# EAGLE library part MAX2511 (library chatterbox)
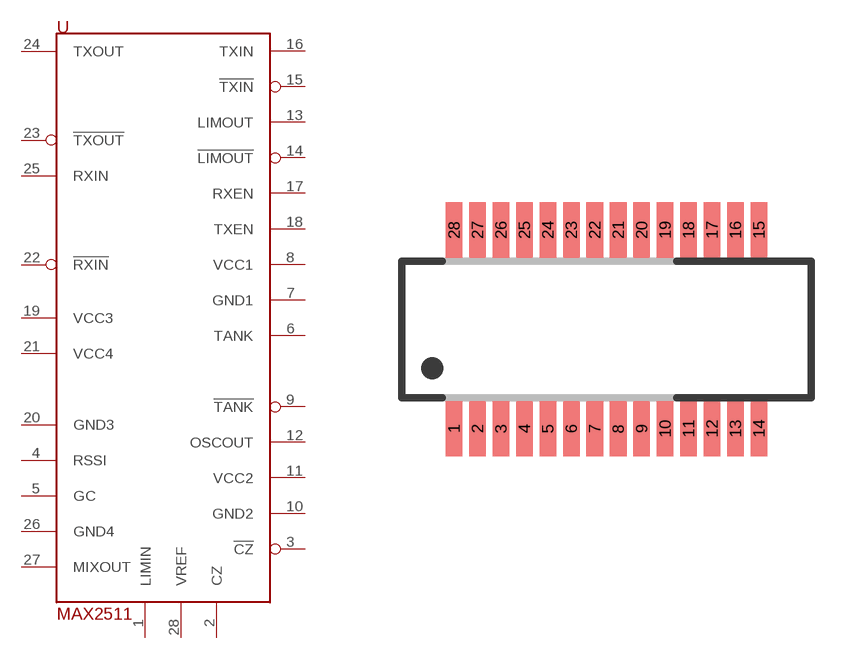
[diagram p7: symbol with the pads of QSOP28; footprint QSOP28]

Designator prefix -

## MAX25110  [QSOP28]
1  LIMIN  pas
2  CZ  pas
3  !CZ  pas
4  RSSI  pas
5  GC  pas
6  TANK  pas
7  GND1  pwr
8  VCC1  pwr
9  !TANK  pas
10  GND2  pwr
11  VCC2  pwr
12  OSCOUT  pas
13  LIMOUT  pas
14  !LIMOUT  pas
15  !TXIN  pas
16  TXIN  pas
17  RXEN  pas
18  TXEN  pas
19  VCC3  pwr
20  GND3  pwr
21  VCC4  pwr
22  !RXIN  pas
23  !TXOUT  pas
24  TXOUT  pas
25  RXIN  pas
26  GND4  pwr
27  MIXOUT  pas
28  VREF  pas

## Footprint QSOP28 (pad centres in mm)
QSOP
smd 0.45 x 1.5: 1 -2.857,-2.69; 2 -2.223,-2.69; 3 -1.587,-2.69; 4 -0.953,-2.69; 5 -0.318,-2.69; 6 0.318,-2.69; 7 0.953,-2.69; 8 1.587,-2.69; 9 2.223,-2.69; 10 2.857,-2.69; 11 3.493,-2.69; 12 4.128,-2.69; 13 4.763,-2.69; 14 5.397,-2.69; 15 5.397,2.69; 16 4.763,2.69; 17 4.128,2.69; 18 3.493,2.69; 19 2.857,2.69; 20 2.223,2.69; 21 1.587,2.69; 22 0.953,2.69; 23 0.318,2.69; 24 -0.318,2.69; 25 -0.953,2.69; 26 -1.587,2.69; 27 -2.223,2.69; 28 -2.857,2.69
